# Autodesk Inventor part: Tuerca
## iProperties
Shininess: 64.0
Length Units: 11272
Angle Units: 11279
Time Units: 11290
Mass Units: 11286
Length Display Precision: 3
Angle Display Precision: 2
Compacted: True
Part Number: Tuerca
Document SubType Name: Modeling
Created: 2005-06
Designer: alek
Manufacturer: Standard
Standards Organization: Custom
Density: 0.0
Volumn: 0.0
Area: 0.0
PropertySet Name: Model Information
Control State: 0
Master: False
Checked Out: False
Author: alek
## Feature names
1. Extrusion1
2. Hole1
3. Revolution1
4. Mirror1
